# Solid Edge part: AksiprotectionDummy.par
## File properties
Author: morva
Template: iso metric part.par
Last saved by: morva
Revision: 6
Application: Solid Edge
Density: 1005.57522819632 kg/m^3
Accuracy: 0.990
Username: morva
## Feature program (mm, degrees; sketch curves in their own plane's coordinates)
sketch for "unnamed Protrusion 1" plane through (0, 0, 0) normal (0, -1, 0) x-axis (1, 0, 0)
  line (39.5, -29) -> (-39.5, -29)
  line (-39.5, -29) -> (-39.5, 29)
  line (-39.5, 29) -> (39.5, 29)
  line (39.5, 29) -> (39.5, -29)
  dimension (linear) = 39.5
  dimension (linear) = 39.5
extrude "unnamed Protrusion 1" add finite 11 along -normal
sketch for "ExtrudedCutout_1" plane through (0, 11, 0) normal (0, 1, 0) x-axis (-1, 0, 0)
extrude "ExtrudedCutout_1" cut finite 4.8758 along -normal
sketch for "ExtrudedCutout_2" plane through (0, 11, 0) normal (0, 1, 0) x-axis (0, 0, -1)
  line (-29, 6.5) -> (-29, 10.5)
  line (-29, 10.5) -> (-26, 10.5)
  line (-26, 10.5) -> (-26, 6.5)
  line (-29, 6.5) -> (-26, 6.5)
  dimension (linear) = 29
  dimension (linear) = 29
extrude "ExtrudedCutout_2" cut finite 5.5671 along -normal
sketch for "ExtrudedCutout_3" plane through (0, 11, 0) normal (0, 1, 0) x-axis (0, 0, 1)
  line (-27, -39.5) -> (-27, -36.5)
  line (-27, -36.5) -> (5, -36.5)
  line (5, -36.5) -> (5, -39.5)
  line (-27, -39.5) -> (5, -39.5)
  dimension (linear) = 27
  dimension (linear) = 27
extrude "ExtrudedCutout_3" cut finite 5.7698 along -normal
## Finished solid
Body 1: solid body, 18 faces, 48 edges, 32 vertices.
  Faces by surface: plane 18
  Edges by curve: line 48
Bounding box of the edges (mm): 79.000 x 11.000 x 58.000, from (-39.5, 0, -29) to (39.5, 11, 29).
Planar faces by outward normal: +x 3, +y 4, +z 3, -x 4, -y 1, -z 3
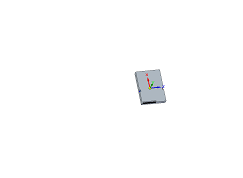
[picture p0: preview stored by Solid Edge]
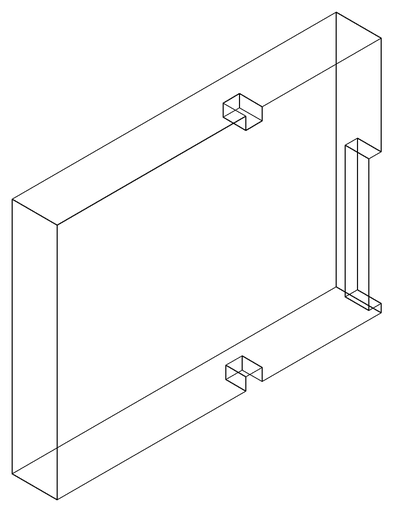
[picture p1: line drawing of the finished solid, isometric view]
